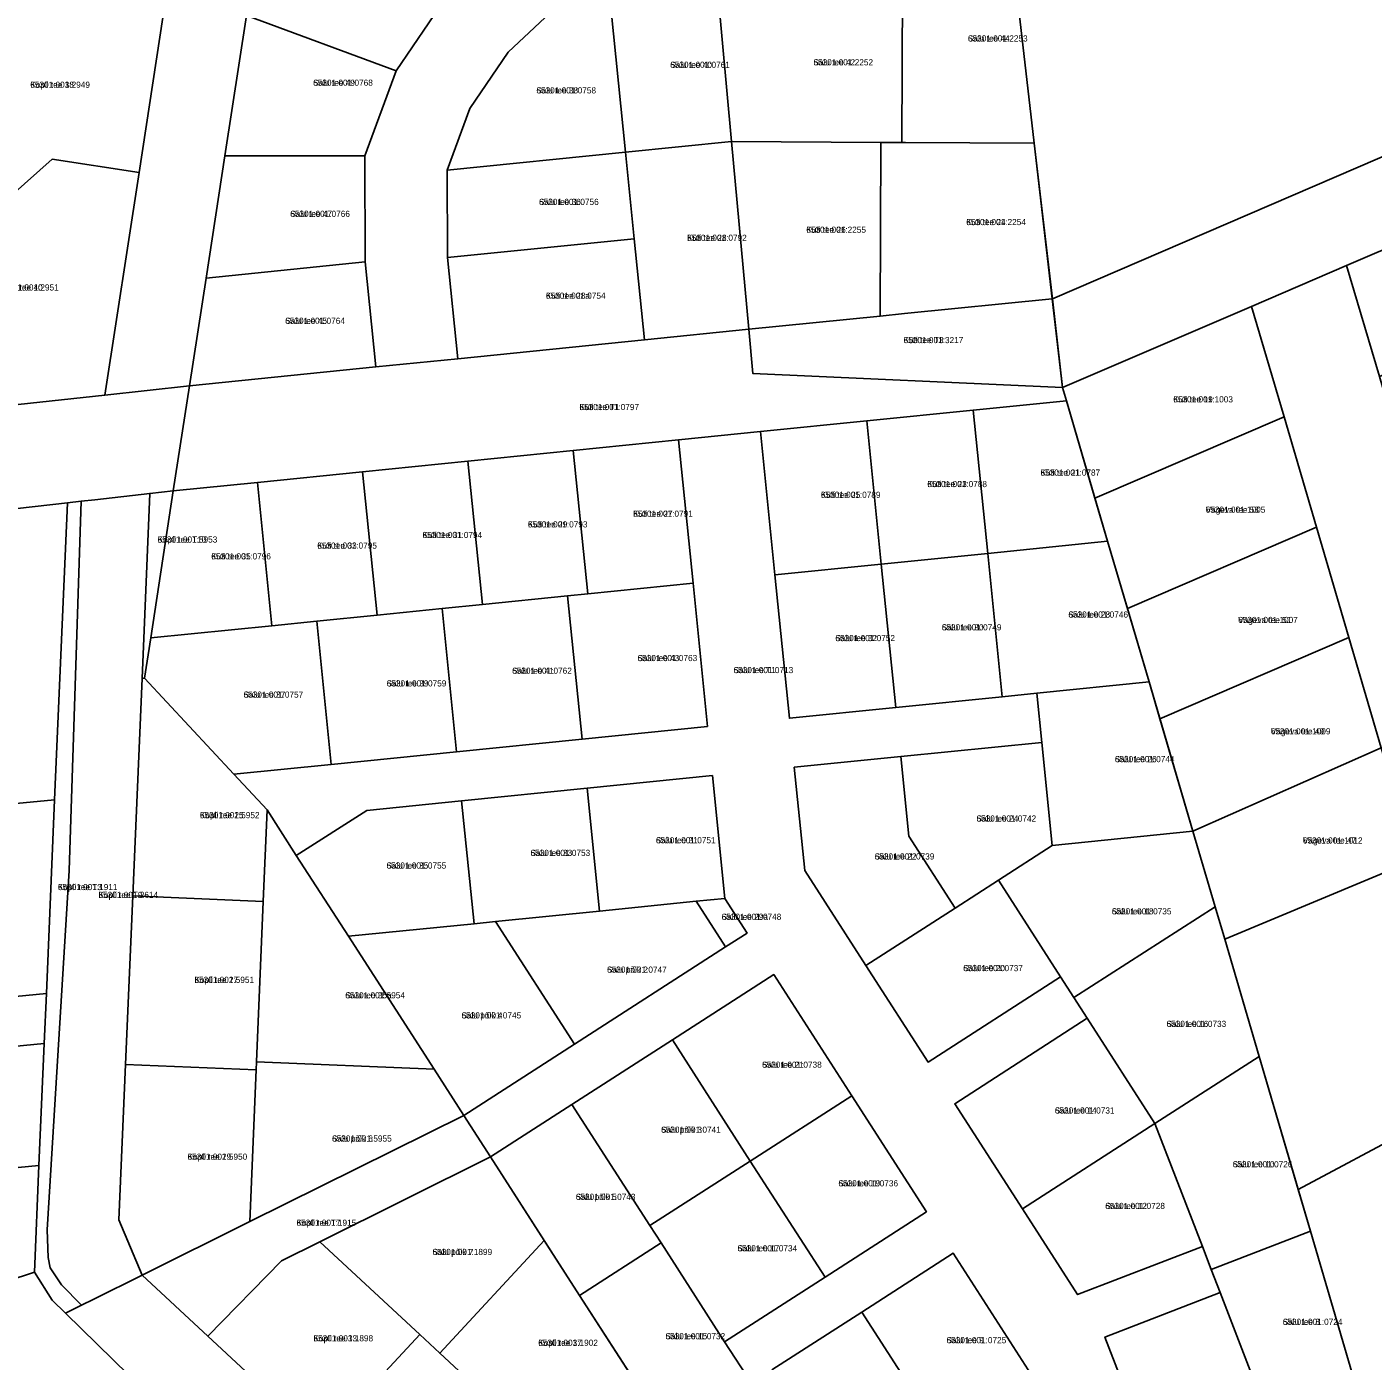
# Model space of a CAD drawing. Extents: x 543236 to 563717, y 6566033 to 6588992.
# Drawn here: x 545303.2 to 545630.4, y 6584287.7 to 6584611.9 of the extents above; entities that cross this region are included whole.
import ezdxf

# ---------------------------------------------------------------- set-up
doc = ezdxf.new("R2010")
doc.units = 0
for name, color, linetype in [('L_AADRESS', 7, 'Continuous'), ('PIIR', 7, 'Continuous'), ('TUNNUS', 7, 'Continuous')]:
    doc.layers.add(name, color=color, linetype=linetype)

msp = doc.modelspace()

# ---------------------------------------------------------------- linework, layer by layer
at = {"layer": 'PIIR'}
for points in [[(545522.71, 6584801.88), (545515.72, 6584861.42), (545540.95, 6584848.28), (545568.44, 6584833.94), (545595.9, 6584819.6), (545623.37, 6584805.21), (545650.89, 6584790.87), (545654.59, 6584788.95), (545726.79, 6584620.99), (545552.43, 6584545.79), (545548.01, 6584583.61), (545542.31, 6584632.89), (545539.87, 6584653.16), (545534.53, 6584699.52), (545531.48, 6584725.86), (545531.11, 6584728.87), (545530.7, 6584731.91)], [(545554.87, 6584524.21), (545552.43, 6584545.79), (545726.79, 6584620.99), (545839.95, 6584669.53), (545872.72, 6584675.22), (545888.44, 6584667.02), (545877.22, 6584662.72), (545831.24, 6584642.97), (545781.01, 6584621.34), (545744.13, 6584605.54), (545732.55, 6584600.53), (545727.05, 6584598.13), (545698.86, 6584586.05), (545669.91, 6584573.6), (545623.89, 6584553.85), (545600.84, 6584543.9)], [(545361.68, 6584647.93), (545381.51, 6584634.53), (545404.83, 6584618.77), (545392.96, 6584601.19), (545356.56, 6584614.6)], [(545516.98, 6584633.03), (545542.31, 6584632.89), (545548.01, 6584583.61), (545516.7, 6584583.77), (545515.81, 6584583.77), (545516.02, 6584621.03), (545516.91, 6584621.03)], [(545277.67, 6584618.06), (545301, 6584614.46), (545317.48, 6584629.07), (545338.05, 6584625.9), (545330.46, 6584576.45), (545309.36, 6584579.72), (545292.84, 6584565.08), (545270.05, 6584568.59)], [(545420.17, 6584605.74), (545436.83, 6584621.46), (545444.63, 6584621.42), (545448.67, 6584581.39), (545405.37, 6584577.02), (545410.89, 6584592.01)], [(545444.63, 6584621.42), (545471.07, 6584621.27), (545474.47, 6584583.99), (545448.67, 6584581.39)], [(545471.07, 6584621.27), (545516.02, 6584621.03), (545515.81, 6584583.77), (545510.77, 6584583.8), (545474.47, 6584583.99)], [(545356.56, 6584614.6), (545392.96, 6584601.19), (545385.36, 6584580.57), (545351.31, 6584580.52)], [(545448.67, 6584581.39), (545474.47, 6584583.99), (545478.63, 6584538.38), (545453.27, 6584535.82), (545450.79, 6584560.38)], [(545474.47, 6584583.99), (545510.77, 6584583.8), (545510.61, 6584541.61), (545478.63, 6584538.38)], [(545510.77, 6584583.8), (545515.81, 6584583.77), (545516.7, 6584583.77), (545548.01, 6584583.61), (545552.37, 6584545.82), (545516.49, 6584542.2), (545510.61, 6584541.61)], [(545351.31, 6584580.52), (545385.36, 6584580.57), (545385.4, 6584554.76), (545346.75, 6584550.82)], [(545405.37, 6584577.02), (545448.67, 6584581.39), (545450.79, 6584560.38), (545405.4, 6584555.8)], [(545270.05, 6584568.59), (545292.84, 6584565.08), (545309.36, 6584579.72), (545330.46, 6584576.45), (545322.14, 6584522.42), (545261.91, 6584515.9)], [(545669.91, 6584573.6), (545677.82, 6584546.65), (545631.89, 6584526.9), (545623.89, 6584553.85)], [(545405.4, 6584555.8), (545450.79, 6584560.38), (545453.27, 6584535.82), (545407.9, 6584531.24)], [(545346.75, 6584550.82), (545385.4, 6584554.76), (545388, 6584529.23), (545342.72, 6584524.66)], [(545623.89, 6584553.85), (545631.89, 6584526.9), (545639.8, 6584499.96), (545647.72, 6584473.02), (545655.63, 6584446.08), (545663.55, 6584419.13), (545640.35, 6584409.42), (545632.34, 6584436.69), (545624.47, 6584463.49), (545616.59, 6584490.28), (545608.72, 6584517.08), (545600.84, 6584543.9)], [(545478.63, 6584538.38), (545510.61, 6584541.61), (545516.49, 6584542.2), (545552.37, 6584545.82), (545554.87, 6584524.21), (545479.61, 6584527.65)], [(545600.84, 6584543.9), (545608.72, 6584517.08), (545562.78, 6584497.34), (545555.82, 6584521.04), (545554.87, 6584524.21)], [(545338.78, 6584499.13), (545342.72, 6584524.66), (545388, 6584529.23), (545407.9, 6584531.24), (545453.27, 6584535.82), (545478.63, 6584538.38), (545479.61, 6584527.65), (545554.87, 6584524.21), (545555.82, 6584521.04), (545533.21, 6584518.76), (545507.34, 6584516.15), (545481.47, 6584513.54), (545461.57, 6584511.53), (545435.98, 6584508.94), (545410.39, 6584506.36), (545384.8, 6584503.78), (545359.21, 6584501.19)], [(545039.38, 6584478.03), (545193.77, 6584499.13), (545195.26, 6584508.58), (545207.54, 6584510.01), (545224.73, 6584511.88), (545261.91, 6584515.9), (545322.14, 6584522.42), (545342.72, 6584524.66), (545338.78, 6584499.13), (545333.06, 6584498.5), (545319.7, 6584496.98), (545316.38, 6584496.6), (545313.05, 6584496.22), (545220.82, 6584485.81), (545222.15, 6584494.52), (545192.81, 6584492.77), (545123.15, 6584483.61), (545122.61, 6584483.53), (545086.15, 6584478.17), (545038.85, 6584471.36)], [(545533.21, 6584518.76), (545555.82, 6584521.04), (545565.86, 6584486.88), (545536.72, 6584483.94)], [(545507.34, 6584516.15), (545533.21, 6584518.76), (545536.72, 6584483.94), (545510.85, 6584481.33)], [(545481.47, 6584513.54), (545507.34, 6584516.15), (545510.85, 6584481.33), (545484.99, 6584478.71)], [(545608.72, 6584517.08), (545616.59, 6584490.28), (545570.66, 6584470.54), (545565.86, 6584486.88), (545562.78, 6584497.34)], [(545435.98, 6584508.94), (545461.57, 6584511.53), (545465.09, 6584476.71), (545439.5, 6584474.12)], [(545410.39, 6584506.36), (545435.98, 6584508.94), (545439.5, 6584474.12), (545434.61, 6584473.63), (545413.91, 6584471.54)], [(545384.8, 6584503.78), (545410.39, 6584506.36), (545413.91, 6584471.54), (545404.14, 6584470.55), (545388.32, 6584468.95)], [(545359.21, 6584501.19), (545384.8, 6584503.78), (545388.32, 6584468.95), (545373.66, 6584467.48), (545362.73, 6584466.37)], [(545316.38, 6584496.6), (545319.7, 6584496.98), (545333.06, 6584498.5), (545331.19, 6584453.54), (545328.92, 6584400.71), (545327.19, 6584359.76), (545325.58, 6584322.02), (545331.19, 6584308.57), (545319.44, 6584302.75), (545316.44, 6584301.26), (545311.62, 6584306.18), (545308.87, 6584310.33), (545308.36, 6584312.85), (545308.13, 6584319.57), (545313.48, 6584406.89)], [(545331.77, 6584453.59), (545331.19, 6584453.54), (545333.06, 6584498.5), (545338.78, 6584499.13), (545333.3, 6584463.39)], [(545338.78, 6584499.13), (545359.21, 6584501.19), (545362.73, 6584466.37), (545333.3, 6584463.39)], [(545220.82, 6584485.81), (545313.05, 6584496.22), (545309.95, 6584424.05), (545208.95, 6584414.4)], [(545313.05, 6584496.22), (545316.38, 6584496.6), (545313.48, 6584406.89), (545308.13, 6584319.57), (545308.36, 6584312.85), (545308.87, 6584310.33), (545311.62, 6584306.18), (545316.44, 6584301.26), (545312.61, 6584299.31), (545309.36, 6584302.45), (545305.02, 6584309.24), (545306.14, 6584335.22), (545307.41, 6584364.86), (545307.93, 6584376.97), (545309.95, 6584424.05)], [(545616.59, 6584490.28), (545624.47, 6584463.49), (545578.53, 6584443.74), (545575.91, 6584452.72), (545570.66, 6584470.54)], [(545536.72, 6584483.94), (545565.86, 6584486.88), (545575.91, 6584452.72), (545548.65, 6584449.96), (545540.24, 6584449.11)], [(545510.85, 6584481.33), (545536.72, 6584483.94), (545540.24, 6584449.11), (545514.37, 6584446.5)], [(545484.99, 6584478.71), (545510.85, 6584481.33), (545514.37, 6584446.5), (545488.5, 6584443.89)], [(545434.61, 6584473.63), (545439.5, 6584474.12), (545465.09, 6584476.71), (545468.6, 6584441.88), (545438.13, 6584438.81)], [(545404.14, 6584470.55), (545413.91, 6584471.54), (545434.61, 6584473.63), (545438.13, 6584438.81), (545407.65, 6584435.73)], [(545373.66, 6584467.48), (545388.32, 6584468.95), (545404.14, 6584470.55), (545407.65, 6584435.73), (545377.18, 6584432.65)], [(545333.3, 6584463.39), (545362.73, 6584466.37), (545373.66, 6584467.48), (545377.18, 6584432.65), (545353.53, 6584430.26), (545331.77, 6584453.59)], [(545624.47, 6584463.49), (545632.34, 6584436.69), (545586.58, 6584416.41), (545578.53, 6584443.74)], [(545360.65, 6584399.36), (545328.92, 6584400.71), (545331.19, 6584453.54), (545331.77, 6584453.59), (545353.53, 6584430.26), (545361.58, 6584421.64)], [(545548.65, 6584449.96), (545575.91, 6584452.72), (545586.58, 6584416.41), (545552.39, 6584412.95), (545549.86, 6584438.02)], [(545515.58, 6584434.56), (545549.86, 6584438.02), (545552.39, 6584412.95), (545539.31, 6584404.54), (545528.78, 6584397.76), (545517.53, 6584415.24)], [(545632.34, 6584436.69), (545640.35, 6584409.42), (545594.3, 6584390.16), (545591.97, 6584398.08), (545586.56, 6584416.41), (545586.58, 6584416.41)], [(545489.71, 6584431.95), (545515.58, 6584434.56), (545517.53, 6584415.24), (545528.78, 6584397.76), (545507.09, 6584383.8), (545492.24, 6584406.88)], [(545439.33, 6584426.87), (545469.81, 6584429.94), (545472.82, 6584400.09), (545465.85, 6584399.39), (545442.35, 6584397.02)], [(545408.86, 6584423.79), (545439.33, 6584426.87), (545442.35, 6584397.02), (545417.13, 6584394.47), (545411.87, 6584393.94)], [(545208.95, 6584414.4), (545309.95, 6584424.05), (545307.93, 6584376.97), (545235.18, 6584369.92)], [(545368.66, 6584410.5), (545385.82, 6584421.46), (545408.86, 6584423.79), (545411.87, 6584393.94), (545381.37, 6584390.89)], [(545360.65, 6584399.36), (545361.58, 6584421.64), (545368.66, 6584410.5), (545381.37, 6584390.89), (545402.16, 6584358.6), (545359.01, 6584360.42)], [(545539.31, 6584404.54), (545552.39, 6584412.95), (545586.58, 6584416.41), (545591.97, 6584398.08), (545557.67, 6584376.01), (545554.43, 6584381.05)], [(545594.3, 6584390.16), (545640.35, 6584409.42), (545667.39, 6584358.85), (545612.18, 6584329.34), (545602.67, 6584361.71)], [(545507.09, 6584383.8), (545528.78, 6584397.76), (545539.31, 6584404.54), (545554.43, 6584381.05), (545522.21, 6584360.31)], [(545358.92, 6584358.41), (545327.19, 6584359.76), (545328.92, 6584400.71), (545360.65, 6584399.36), (545359.01, 6584360.42)], [(545465.85, 6584399.39), (545472.82, 6584400.09), (545478.24, 6584391.68), (545472.99, 6584388.3)], [(545417.13, 6584394.47), (545442.35, 6584397.02), (545465.85, 6584399.39), (545472.99, 6584388.3), (545436.3, 6584364.69)], [(545557.67, 6584376.01), (545591.97, 6584398.08), (545594.3, 6584390.16), (545602.67, 6584361.71), (545577.36, 6584345.42), (545560.92, 6584370.96)], [(545402.16, 6584358.6), (545381.37, 6584390.89), (545411.87, 6584393.94), (545417.13, 6584394.47), (545436.3, 6584364.69), (545409.38, 6584347.37)], [(545460.07, 6584365.71), (545484.73, 6584381.59), (545503.67, 6584352.16), (545479.01, 6584336.28)], [(545235.18, 6584369.92), (545307.93, 6584376.97), (545307.41, 6584364.86), (545241.91, 6584358.52)], [(545528.7, 6584350.22), (545560.92, 6584370.96), (545577.36, 6584345.42), (545545.14, 6584324.68)], [(545241.91, 6584358.52), (545307.41, 6584364.86), (545306.14, 6584335.22), (545258.4, 6584330.6)], [(545435.68, 6584350.02), (545460.07, 6584365.71), (545479.01, 6584336.28), (545454.63, 6584320.59)], [(545577.36, 6584345.42), (545602.67, 6584361.71), (545615.16, 6584319.21), (545591.04, 6584309.91), (545588.89, 6584315.51)], [(545357.37, 6584321.57), (545331.19, 6584308.57), (545325.58, 6584322.02), (545327.19, 6584359.76), (545358.92, 6584358.41)], [(545359.01, 6584360.42), (545402.16, 6584358.6), (545409.38, 6584347.37), (545357.37, 6584321.57), (545358.92, 6584358.41)], [(545612.18, 6584329.34), (545667.39, 6584358.85), (545675.07, 6584344.48), (545698.18, 6584306.68), (545692.06, 6584302.94), (545696.57, 6584295.46), (545702.81, 6584299.16), (545716.82, 6584276.21), (545641.37, 6584230.07), (545632.88, 6584258.94), (545625.8, 6584283.01), (545615.16, 6584319.21)], [(545479.01, 6584336.28), (545503.67, 6584352.16), (545521.83, 6584323.95), (545497.17, 6584308.08)], [(545415.88, 6584337.28), (545435.68, 6584350.02), (545454.63, 6584320.59), (545457.33, 6584316.38), (545437.53, 6584303.64)], [(545331.19, 6584308.57), (545357.37, 6584321.57), (545409.38, 6584347.37), (545415.88, 6584337.28), (545374.36, 6584316.68), (545365.08, 6584312.07), (545347.2, 6584293.73)], [(545545.14, 6584324.68), (545577.36, 6584345.42), (545588.89, 6584315.51), (545558.56, 6584303.83)], [(545258.4, 6584330.6), (545306.14, 6584335.22), (545305.02, 6584309.24), (545277.65, 6584300.25)], [(545374.36, 6584316.68), (545415.88, 6584337.28), (545428.95, 6584316.96), (545403.55, 6584289.59), (545398.67, 6584294.12)], [(545454.63, 6584320.59), (545479.01, 6584336.28), (545497.17, 6584308.08), (545472.78, 6584292.38), (545457.33, 6584316.38)], [(545591.04, 6584309.91), (545615.16, 6584319.21), (545625.8, 6584283.01), (545604.56, 6584274.83), (545593.2, 6584304.32)], [(545347.2, 6584293.73), (545365.08, 6584312.07), (545374.36, 6584316.68), (545398.67, 6584294.12), (545374.65, 6584268.24)], [(545403.55, 6584289.59), (545428.95, 6584316.96), (545437.53, 6584303.64), (545451.4, 6584282.08), (545432.99, 6584262.25), (545425.51, 6584269.2)], [(545437.53, 6584303.64), (545457.33, 6584316.38), (545472.78, 6584292.38), (545479.27, 6584282.29), (545459.47, 6584269.55)], [(545506.15, 6584299.59), (545528.32, 6584313.86), (545547.27, 6584284.42), (545525.09, 6584270.15)], [(545277.65, 6584300.25), (545305.02, 6584309.24), (545309.36, 6584302.45), (545312.61, 6584299.31), (545328.02, 6584284.27), (545329.53, 6584282.87), (545310.17, 6584263.01), (545303.83, 6584258.96), (545293.5, 6584275.25), (545288.57, 6584283.02), (545283.65, 6584290.79)], [(545312.61, 6584299.31), (545316.44, 6584301.26), (545319.44, 6584302.75), (545331.19, 6584308.57), (545347.2, 6584293.73), (545374.65, 6584268.24), (545401.49, 6584243.33), (545408.98, 6584236.38), (545441.22, 6584206.45), (545462.52, 6584186.68), (545481.97, 6584168.63), (545461.22, 6584160.63), (545431.23, 6584188.46), (545405.41, 6584212.43), (545378.77, 6584237.16), (545373.41, 6584242.13), (545355.3, 6584258.94), (545333.24, 6584279.42), (545329.53, 6584282.87), (545328.02, 6584284.27)], [(545565.2, 6584293.52), (545593.2, 6584304.32), (545604.56, 6584274.83), (545576.56, 6584264.03)], [(545484.28, 6584285.51), (545506.15, 6584299.59), (545525.09, 6584270.15), (545513.03, 6584262.38), (545503.23, 6584256.08)], [(545374.65, 6584268.24), (545398.67, 6584294.12), (545403.55, 6584289.59), (545425.51, 6584269.2), (545401.49, 6584243.33)]]:
    msp.add_lwpolyline(points, close=True, dxfattribs=at)
for points in [[(545356.56, 6584614.6), (545351.31, 6584580.52), (545346.75, 6584550.82), (545342.72, 6584524.66), (545322.14, 6584522.42), (545330.46, 6584576.45), (545338.05, 6584625.9)], [(545436.83, 6584621.46), (545420.17, 6584605.74), (545410.89, 6584592.01), (545405.37, 6584577.02), (545405.4, 6584555.8), (545407.9, 6584531.24), (545388, 6584529.23), (545385.4, 6584554.76), (545385.36, 6584580.57), (545392.96, 6584601.19), (545404.83, 6584618.77)], [(545479.27, 6584282.29), (545472.78, 6584292.38), (545497.17, 6584308.08), (545521.83, 6584323.95), (545503.67, 6584352.16), (545484.73, 6584381.59), (545460.07, 6584365.71), (545435.68, 6584350.02), (545415.88, 6584337.28), (545409.38, 6584347.37), (545436.3, 6584364.69), (545472.99, 6584388.3), (545478.24, 6584391.68), (545472.82, 6584400.09), (545469.81, 6584429.94), (545439.33, 6584426.87), (545408.86, 6584423.79), (545385.82, 6584421.46), (545368.66, 6584410.5), (545361.58, 6584421.64), (545353.53, 6584430.26), (545377.18, 6584432.65), (545407.65, 6584435.73), (545438.13, 6584438.81), (545468.6, 6584441.88), (545465.09, 6584476.71), (545461.57, 6584511.53), (545481.47, 6584513.54), (545484.99, 6584478.71), (545488.5, 6584443.89), (545514.37, 6584446.5), (545540.24, 6584449.11), (545548.65, 6584449.96), (545549.86, 6584438.02), (545515.58, 6584434.56), (545489.71, 6584431.95), (545492.24, 6584406.88), (545507.09, 6584383.8), (545522.21, 6584360.31), (545554.43, 6584381.05), (545557.67, 6584376.01), (545560.92, 6584370.96), (545528.7, 6584350.22), (545545.14, 6584324.68), (545558.56, 6584303.83), (545588.89, 6584315.51), (545591.04, 6584309.91), (545593.2, 6584304.32), (545565.2, 6584293.52), (545576.56, 6584264.03)], [(545547.27, 6584284.42), (545528.32, 6584313.86), (545506.15, 6584299.59), (545484.28, 6584285.51)]]:
    msp.add_lwpolyline(points, dxfattribs=at)

# ---------------------------------------------------------------- texts
at = {"layer": 'L_AADRESS'}
for s, p in [('Salu tee 44', (545531.91, 6584608.32)), ('Salu tee 40', (545459.55, 6584601.91)), ('Salu tee 42', (545494.35, 6584602.52)), ('Kopli tee 38', (545304.03, 6584597.07)), ('Salu tee 49', (545372.78, 6584597.56)), ('Salu tee 38', (545427.02, 6584595.7)), ('Salu tee 36', (545427.67, 6584568.6)), ('Salu tee 47', (545367.21, 6584565.7)), ('Küti tee 24', (545531.49, 6584563.7)), ('Küti tee 28', (545463.65, 6584559.88)), ('Küti tee 26', (545492.62, 6584561.84)), ('Kopli tee 40', (545296.44, 6584547.81)), ('Küti tee 28a', (545429.34, 6584545.81)), ('Salu tee 45', (545365.99, 6584539.71)), ('Küti tee T3', (545516.28, 6584535.02)), ('Küti tee 19', (545581.81, 6584520.62)), ('Küti tee T1', (545437.48, 6584518.75)), ('Küti tee 23', (545522.03, 6584500.04)), ('Küti tee 21', (545549.54, 6584502.82)), ('Küti tee 25', (545496.16, 6584497.43)), ('Vägeva tee 53', (545589.69, 6584493.81)), ('Küti tee 29', (545424.95, 6584490.24)), ('Küti tee 27', (545450.54, 6584492.83)), ('Küti tee 31', (545399.35, 6584487.66)), ('Kopli tee T10', (545334.98, 6584486.55)), ('Küti tee 33', (545373.77, 6584485.08)), ('Küti tee 35', (545348.01, 6584482.47)), ('Salu tee 28', (545556.31, 6584468.33)), ('Salu tee 30', (545525.55, 6584465.22)), ('Vägeva tee 51', (545597.57, 6584467.01)), ('Salu tee 32', (545499.68, 6584462.61)), ('Salu tee 43', (545451.61, 6584457.76)), ('Salu tee 41', (545421.14, 6584454.68)), ('Salu tee T1', (545474.94, 6584454.84)), ('Salu tee 39', (545390.65, 6584451.6)), ('Salu tee 37', (545355.86, 6584448.87)), ('Vägeva tee 49', (545605.51, 6584439.95)), ('Salu tee 26', (545567.61, 6584433.19)), ('Kopli tee 25', (545345.25, 6584419.58)), ('Salu tee 24', (545533.98, 6584418.76)), ('Salu tee 31', (545456.08, 6584413.48)), ('Vägeva tee 47', (545613.31, 6584413.43)), ('Salu tee 33', (545425.6, 6584410.41)), ('Salu tee 22', (545509.25, 6584409.55)), ('Salu tee 35', (545390.61, 6584407.34)), ('Kopli tee T3', (545310.73, 6584402.11)), ('Kopli tee T9', (545320.6, 6584400.2)), ('Salu tee 18', (545566.87, 6584396.21)), ('Salu tee 29a', (545472.05, 6584394.89)), ('Salu põik 2', (545444.2, 6584382.04)), ('Salu tee 20', (545530.76, 6584382.42)), ('Kopli tee 27', (545343.92, 6584379.56)), ('Salu tee 35a', (545380.58, 6584375.81)), ('Salu põik 4', (545408.83, 6584370.93)), ('Salu tee 16', (545580.17, 6584368.86)), ('Salu tee 21', (545481.87, 6584358.94)), ('Salu tee 14', (545553.03, 6584347.82)), ('Salu põik 3', (545457.34, 6584343.15)), ('Salu põik 6', (545377.36, 6584341)), ('Kopli tee 29', (545342.25, 6584336.59)), ('Salu tee 10', (545596.26, 6584334.75)), ('Salu tee 19', (545500.42, 6584330.12)), ('Salu põik 5', (545436.61, 6584326.83)), ('Salu tee 12', (545565.28, 6584324.62)), ('Kopli tee T7', (545368.74, 6584320.55)), ('Salu põik 7', (545401.77, 6584313.44)), ('Salu tee 17', (545475.9, 6584314.33)), ('Salu tee 8', (545608.42, 6584296.46)), ('Kopli tee 33', (545372.85, 6584292.46)), ('Kopli tee 37', (545427.47, 6584291.37)), ('Salu tee 15', (545458.4, 6584292.97)), ('Salu tee 9', (545526.71, 6584292.01))]:
    msp.add_text(s, height=1.5, dxfattribs=at).set_placement(p)
at = {"layer": 'TUNNUS'}
for s, p in [('65301:001:2253', (545531.91, 6584608.32)), ('65301:001:0761', (545459.55, 6584601.91)), ('65301:001:2252', (545494.35, 6584602.52)), ('65301:001:2949', (545304.03, 6584597.07)), ('65301:001:0768', (545372.78, 6584597.56)), ('65301:001:0758', (545427.02, 6584595.7)), ('65301:001:0756', (545427.67, 6584568.6)), ('65301:001:0766', (545367.21, 6584565.7)), ('65301:001:2254', (545531.49, 6584563.7)), ('65301:001:0792', (545463.65, 6584559.88)), ('65301:001:2255', (545492.62, 6584561.84)), ('65301:001:2951', (545296.44, 6584547.81)), ('65301:001:0754', (545429.34, 6584545.81)), ('65301:001:0764', (545365.99, 6584539.71)), ('65301:001:3217', (545516.28, 6584535.02)), ('65301:001:1003', (545581.81, 6584520.62)), ('65301:001:0797', (545437.48, 6584518.75)), ('65301:001:0788', (545522.03, 6584500.04)), ('65301:001:0787', (545549.54, 6584502.82)), ('65301:001:0789', (545496.16, 6584497.43)), ('65301:001:1005', (545589.69, 6584493.81)), ('65301:001:0793', (545424.95, 6584490.24)), ('65301:001:0791', (545450.54, 6584492.83)), ('65301:001:0794', (545399.35, 6584487.66)), ('65301:001:5953', (545334.98, 6584486.55)), ('65301:001:0795', (545373.77, 6584485.08)), ('65301:001:0796', (545348.01, 6584482.47)), ('65301:001:0746', (545556.31, 6584468.33)), ('65301:001:0749', (545525.55, 6584465.22)), ('65301:001:1007', (545597.57, 6584467.01)), ('65301:001:0752', (545499.68, 6584462.61)), ('65301:001:0763', (545451.61, 6584457.76)), ('65301:001:0762', (545421.14, 6584454.68)), ('65301:001:0713', (545474.94, 6584454.84)), ('65301:001:0759', (545390.65, 6584451.6)), ('65301:001:0757', (545355.86, 6584448.87)), ('65301:001:1009', (545605.51, 6584439.95)), ('65301:001:0744', (545567.61, 6584433.19)), ('65301:001:5952', (545345.25, 6584419.58)), ('65301:001:0742', (545533.98, 6584418.76)), ('65301:001:0751', (545456.08, 6584413.48)), ('65301:001:1012', (545613.31, 6584413.43)), ('65301:001:0753', (545425.6, 6584410.41)), ('65301:001:0739', (545509.25, 6584409.55)), ('65301:001:0755', (545390.61, 6584407.34)), ('65301:001:1911', (545310.73, 6584402.11)), ('65301:001:2614', (545320.6, 6584400.2)), ('65301:001:0735', (545566.87, 6584396.21)), ('65301:001:0748', (545472.05, 6584394.89)), ('65301:001:0747', (545444.2, 6584382.04)), ('65301:001:0737', (545530.76, 6584382.42)), ('65301:001:5951', (545343.92, 6584379.56)), ('65301:001:5954', (545380.58, 6584375.81)), ('65301:001:0745', (545408.83, 6584370.93)), ('65301:001:0733', (545580.17, 6584368.86)), ('65301:001:0738', (545481.87, 6584358.94)), ('65301:001:0731', (545553.03, 6584347.82)), ('65301:001:0741', (545457.34, 6584343.15)), ('65301:001:5955', (545377.36, 6584341)), ('65301:001:5950', (545342.25, 6584336.59)), ('65301:001:0726', (545596.26, 6584334.75)), ('65301:001:0736', (545500.42, 6584330.12)), ('65301:001:0743', (545436.61, 6584326.83)), ('65301:001:0728', (545565.28, 6584324.62)), ('65301:001:1915', (545368.74, 6584320.55)), ('65301:001:1899', (545401.77, 6584313.44)), ('65301:001:0734', (545475.9, 6584314.33)), ('65301:001:0724', (545608.42, 6584296.46)), ('65301:001:1898', (545372.85, 6584292.46)), ('65301:001:1902', (545427.47, 6584291.37)), ('65301:001:0732', (545458.4, 6584292.97)), ('65301:001:0725', (545526.71, 6584292.01))]:
    msp.add_text(s, height=1.5, dxfattribs=at).set_placement(p)

doc.saveas('drawing.dxf')
